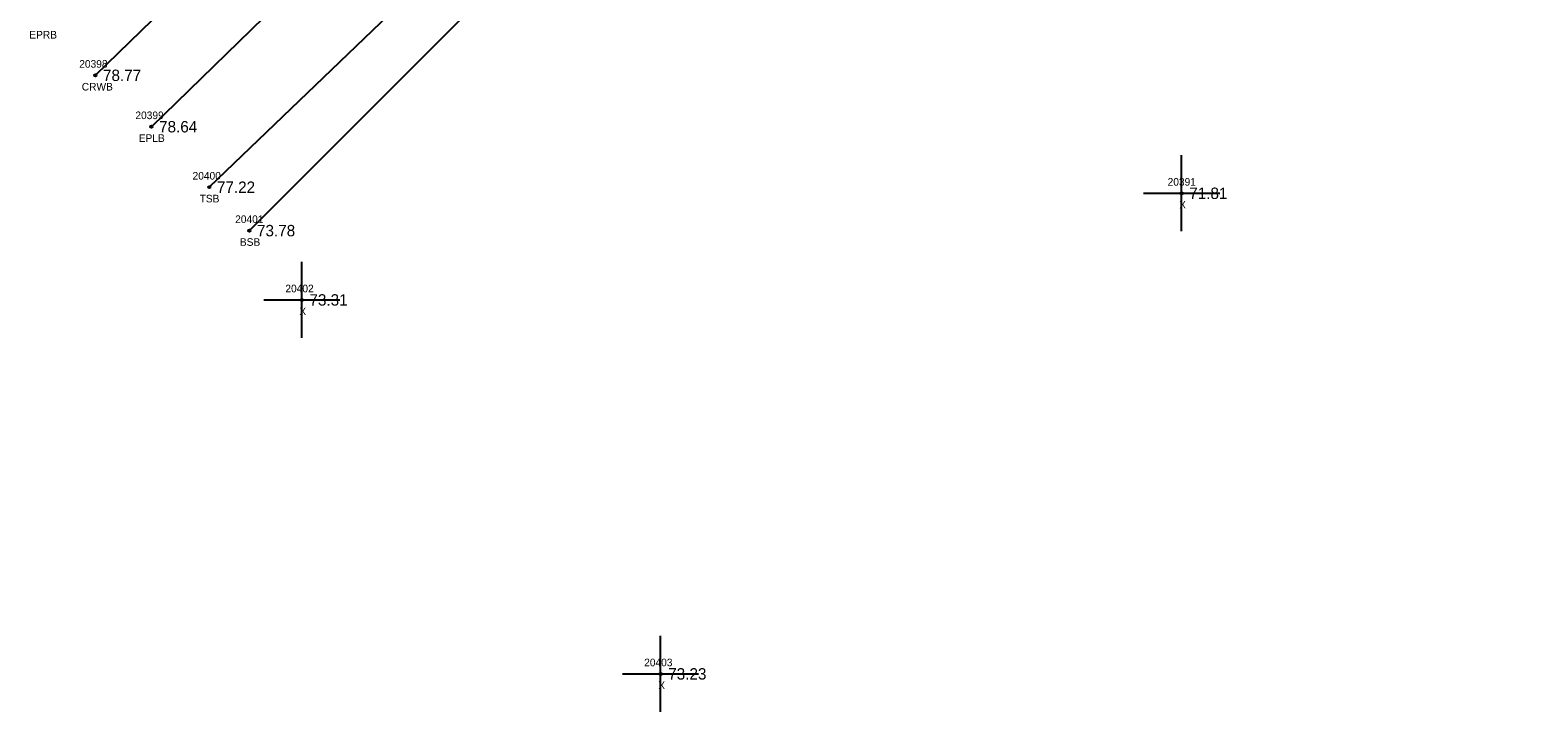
# Model space of a CAD drawing. Extents: x 2505300 to 2506184, y 912965 to 913825.
# Drawn here: x 2505354.7 to 2505552.8, y 912964.8 to 913054.5 of the extents above; entities that cross this region are included whole.
import ezdxf

# ---------------------------------------------------------------- set-up
doc = ezdxf.new("R2010")
doc.units = 0
for name, color, linetype in [('RD_DTM_BkLn1', 7, 'Continuous'), ('RD_DTM_BkLn2', 7, 'Continuous'), ('RD_DTM_BkLn_txCode', 7, 'Continuous'), ('RD_EX_Misc', 7, 'Continuous'), ('RD_EX_Misc_txCode', 7, 'Continuous'), ('RD_EX_Road', 7, 'Continuous'), ('RD_EX_Road_txCode', 7, 'Continuous'), ('RD_EX_TX_Misc_ELEV', 7, 'Continuous'), ('RD_EX_TX_Road_ELEV', 7, 'Continuous'), ('RD_HC_Survey_ELEV', 7, 'Continuous'), ('RD_HC_Survey_txCode', 7, 'Continuous'), ('RD_SMD_Locator', 7, 'Continuous')]:
    doc.layers.add(name, color=color, linetype=linetype)

msp = doc.modelspace()

# ---------------------------------------------------------------- linework, layer by layer
at = {"layer": 'RD_DTM_BkLn1'}
msp.add_lwpolyline([(2505767.92, 913463.52), (2505733.49, 913421.6), (2505698.21, 913380.67), (2505657.08, 913336.16), (2505615.28, 913294.08), (2505578.04, 913257.66), (2505509.81, 913190.87), (2505437.56, 913120.73), (2505363.23, 913048.54)], dxfattribs=at)
at = {"layer": 'RD_DTM_BkLn2'}
for points in [[(2505608.57, 913197.02), (2505580.09, 913207.47), (2505555.7, 913208.91), (2505524.48, 913174.98), (2505452.19, 913104.88), (2505378.2, 913033.83)], [(2505606.77, 913192.45), (2505577.32, 913200.72), (2505558.46, 913202.1), (2505528.34, 913169.89), (2505451.24, 913096.03), (2505383.47, 913028.12)]]:
    msp.add_lwpolyline(points, dxfattribs=at)
at = {"layer": 'RD_EX_Misc'}
for p, q in [((2505505.98, 913028.03), (2505505.98, 913038.03)), ((2505500.98, 913033.03), (2505510.98, 913033.03)), ((2505390.36, 913014.01), (2505390.36, 913024.01)), ((2505385.36, 913019.01), (2505395.36, 913019.01)), ((2505437.51, 912964.84), (2505437.51, 912974.84)), ((2505432.51, 912969.84), (2505442.51, 912969.84))]:
    msp.add_line(p, q, dxfattribs=at)
at = {"layer": 'RD_EX_Road'}
msp.add_lwpolyline([(2505777.56, 913455.88), (2505770.31, 913449.85), (2505741, 913414.45), (2505705.55, 913374.27), (2505664.83, 913329.82), (2505624.02, 913288.23), (2505585.62, 913250.63), (2505516.95, 913183.5), (2505444.27, 913113.56), (2505370.6, 913041.78)], dxfattribs=at)
at = {"layer": 'RD_SMD_Locator'}
for centre in [(2505363.23, 913048.54), (2505370.6, 913041.78), (2505378.2, 913033.83), (2505505.98, 913033.03), (2505383.47, 913028.12), (2505390.36, 913019.01), (2505437.51, 912969.84)]:
    msp.add_circle(centre, 0.15, dxfattribs=at)

# ---------------------------------------------------------------- texts
at = {"layer": 'RD_DTM_BkLn_txCode'}
for s, p in [('20400', (2505376, 913034.83)), ('TSB', (2505376.93, 913031.83)), ('20401', (2505381.6, 913029.12)), ('BSB', (2505382.22, 913026.12))]:
    msp.add_text(s, height=1, dxfattribs=at).set_placement(p)
at = {"layer": 'RD_EX_Misc_txCode'}
for s, p in [('20391', (2505504.14, 913034.03)), ('X', (2505505.66, 913031.03)), ('20402', (2505388.2, 913020.01)), ('X', (2505390.04, 913017.01)), ('20403', (2505435.35, 912970.84)), ('X', (2505437.2, 912967.84))]:
    msp.add_text(s, height=1, dxfattribs=at).set_placement(p)
at = {"layer": 'RD_EX_Road_txCode'}
for s, p in [('EPRB', (2505354.55, 913053.37)), ('20399', (2505368.49, 913042.78)), ('EPLB', (2505368.93, 913039.78))]:
    msp.add_text(s, height=1, dxfattribs=at).set_placement(p)
at = {"layer": 'RD_EX_TX_Misc_ELEV'}
for s, p in [('77.22', (2505379.2, 913033.08)), ('71.81', (2505506.98, 913032.28)), ('73.78', (2505384.47, 913027.37)), ('73.31', (2505391.36, 913018.26)), ('73.23', (2505438.51, 912969.09))]:
    msp.add_text(s, height=1.5, dxfattribs=at).set_placement(p)
at = {"layer": 'RD_EX_TX_Road_ELEV'}
msp.add_text('78.64', height=1.5, dxfattribs=at).set_placement((2505371.6, 913041.03))
at = {"layer": 'RD_HC_Survey_ELEV'}
msp.add_text('78.77', height=1.5, dxfattribs=at).set_placement((2505364.23, 913047.79))
at = {"layer": 'RD_HC_Survey_txCode'}
for s, p in [('20398', (2505361.11, 913049.54)), ('CRWB', (2505361.44, 913046.54))]:
    msp.add_text(s, height=1, dxfattribs=at).set_placement(p)

doc.saveas('drawing.dxf')
